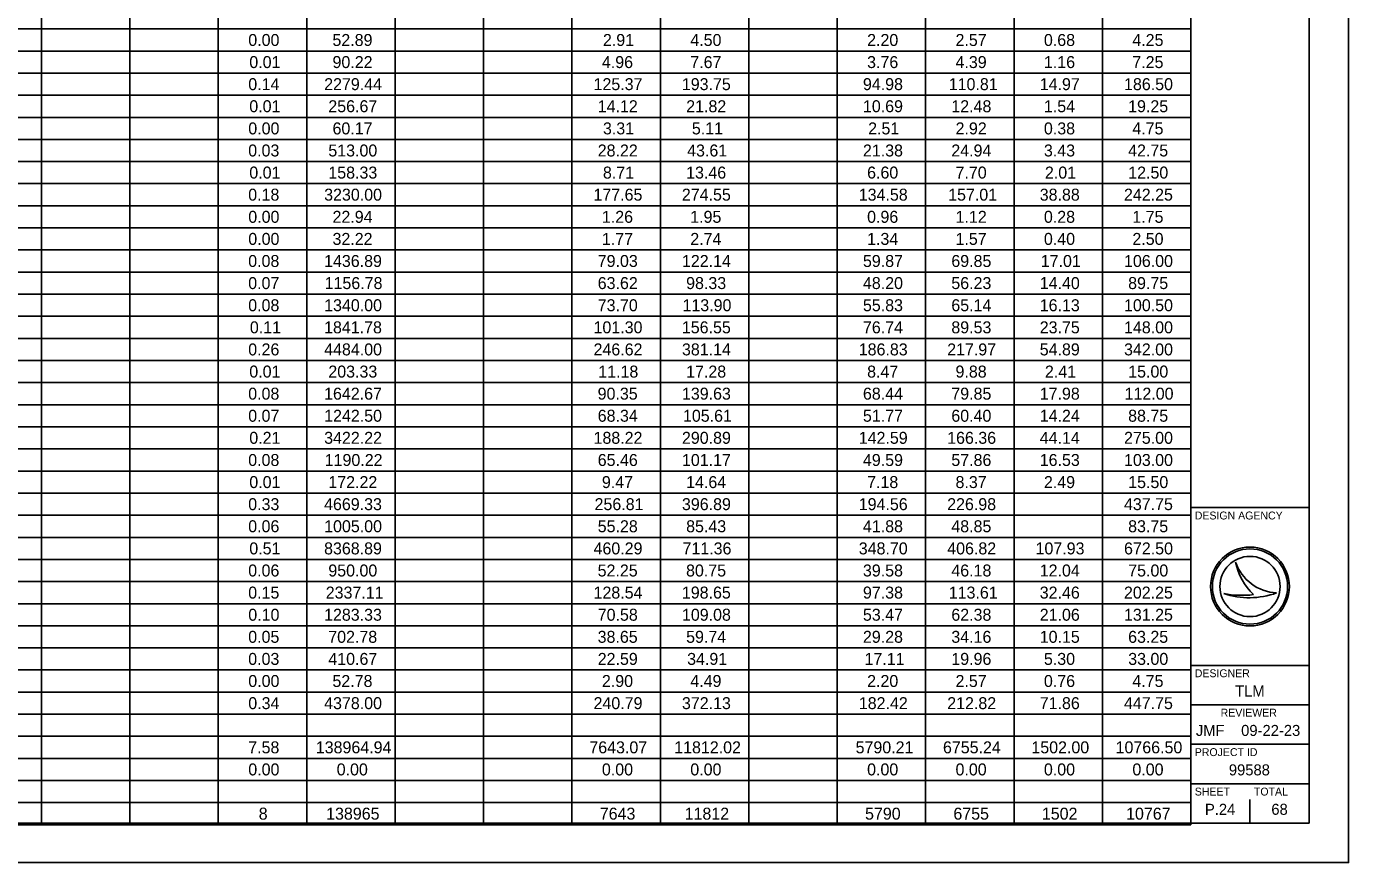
# Model space of a CAD drawing. Extents: x 0 to 34, y 0 to 22.
# Drawn here: x 17.23 to 34, y 0 to 10.6 of the extents above; entities that cross this region are included whole.
import ezdxf

# ---------------------------------------------------------------- set-up
doc = ezdxf.new("R2010")
doc.units = 0
for name, color, linetype in [('SH_Border', 7, 'Continuous'), ('SH_Cut_Line', 7, 'Continuous'), ('SH_Data', 7, 'Continuous'), ('SH_Text', 7, 'Continuous')]:
    doc.layers.add(name, color=color, linetype=linetype)

msp = doc.modelspace()

# ---------------------------------------------------------------- linework, layer by layer
at = {"layer": 'SH_Border'}
for p, q in [((32, 0.5), (32, 21.5)), ((32, 4.5), (33.5, 4.5)), ((32, 2.5), (33.5, 2.5)), ((32, 2), (33.5, 2)), ((32, 1.5), (33.5, 1.5)), ((32, 1), (33.5, 1))]:
    msp.add_line(p, q, dxfattribs=at)
msp.add_lwpolyline([(1.5, 21.5), (33.5, 21.5), (33.5, 0.5), (1.5, 0.5)], close=True, dxfattribs=at)
at = {"layer": 'SH_Cut_Line'}
msp.add_lwpolyline([(0, 0), (34, 0), (34, 22), (0, 22)], close=True, dxfattribs=at)
at = {"layer": 'SH_Data'}
for p, q in [((32.567, 3.81), (32.567, 3.81)), ((32.417, 3.41), (32.417, 3.41)), ((32.75, 3.5), (32.75, 3.5)), ((33.087, 3.419), (33.087, 3.419)), ((32.375, 0.675), (32.375, 0.675)), ((32.75, 0.5), (32.75, 0.8))]:
    msp.add_line(p, q, dxfattribs=at)
for radius in [0.5, 0.477, 0.477, 0.382]:
    msp.add_circle((32.75, 3.5), radius, dxfattribs=at)
for centre, radius, start, end in [((33.116, 3.998), 0.58, 198.9257, 198.9319), ((33.347, 3.97), 0.796, 191.6379, 191.6421), ((33.116, 3.998), 0.58, 198.9319, 267.1657), ((33.347, 3.97), 0.796, 191.6421, 226.0947), ((32.739, 4.37), 1.013, 251.4576, 290.0832), ((32.648, 4.654), 1.266, 259.4964, 259.4995), ((32.739, 4.37), 1.013, 251.4527, 251.4576), ((32.648, 4.654), 1.266, 259.4995, 276.6672)]:
    msp.add_arc(centre, radius, start, end, dxfattribs=at)
at = {"layer": 'SH_Text'}
for p, q in [((17.426, 21.5), (17.426, 0.48)), ((18.547, 21.5), (18.547, 0.48)), ((19.668, 21.5), (19.668, 0.48)), ((20.789, 21.5), (20.789, 0.48)), ((21.91, 21.5), (21.91, 0.48)), ((23.031, 21.5), (23.031, 0.48)), ((24.152, 21.5), (24.152, 0.48)), ((25.274, 21.5), (25.274, 0.48)), ((26.395, 21.5), (26.395, 0.48)), ((27.516, 21.5), (27.516, 0.48)), ((28.637, 21.5), (28.637, 0.48)), ((29.758, 21.5), (29.758, 0.48)), ((30.879, 21.5), (30.879, 0.48)), ((32, 21.5), (32, 0.48)), ((1.5, 10.569), (32, 10.569)), ((1.5, 10.289), (32, 10.289)), ((1.5, 10.009), (32, 10.009)), ((1.5, 9.729), (32, 9.729)), ((1.5, 9.448), (32, 9.448)), ((1.5, 9.168), (32, 9.168)), ((1.5, 8.888), (32, 8.888)), ((1.5, 8.608), (32, 8.608)), ((1.5, 8.327), (32, 8.327)), ((1.5, 8.047), (32, 8.047)), ((1.5, 7.767), (32, 7.767)), ((1.5, 7.486), (32, 7.486)), ((1.5, 7.206), (32, 7.206)), ((1.5, 6.926), (32, 6.926)), ((1.5, 6.646), (32, 6.646)), ((1.5, 6.365), (32, 6.365)), ((1.5, 6.085), (32, 6.085)), ((1.5, 5.805), (32, 5.805)), ((1.5, 5.525), (32, 5.525)), ((1.5, 5.244), (32, 5.244)), ((1.5, 4.964), (32, 4.964)), ((1.5, 4.684), (32, 4.684)), ((1.5, 4.404), (32, 4.404)), ((1.5, 4.123), (32, 4.123)), ((1.5, 3.843), (32, 3.843)), ((1.5, 3.563), (32, 3.563)), ((1.5, 3.282), (32, 3.282)), ((1.5, 3.002), (32, 3.002)), ((1.5, 2.722), (32, 2.722)), ((1.5, 2.442), (32, 2.442)), ((1.5, 2.161), (32, 2.161)), ((1.5, 1.881), (32, 1.881)), ((1.5, 1.601), (32, 1.601)), ((1.5, 1.321), (32, 1.321)), ((1.5, 1.04), (32, 1.04)), ((1.5, 0.76), (32, 0.76)), ((1.5, 0.48), (32, 0.48))]:
    msp.add_line(p, q, dxfattribs=at)

# ---------------------------------------------------------------- texts
at = {"layer": 'SH_Data'}
for s, height, p in [('DESIGN AGENCY', 0.1, (32.05, 4.35)), ('DESIGNER', 0.1, (32.05, 2.35)), ('TLM', 0.14, (32.562, 2.105)), ('REVIEWER', 0.1, (32.378, 1.85)), ('JMF', 0.14, (32.064, 1.605)), ('09-22-23', 0.14, (32.638, 1.605)), ('PROJECT ID', 0.1, (32.05, 1.35)), ('99588', 0.14, (32.482, 1.105)), ('SHEET', 0.1, (32.05, 0.85)), ('TOTAL', 0.1, (32.8, 0.85)), ('P.24', 0.14, (32.179, 0.605)), ('68', 0.14, (33.021, 0.605))]:
    msp.add_text(s, height=height, dxfattribs=at).set_placement(p)
at = {"layer": 'SH_Text'}
for s, height, p in [('0.00', 0.1517, (20.048, 10.353)), ('52.89', 0.1517, (21.115, 10.353)), ('2.91', 0.1517, (24.545, 10.353)), ('4.50', 0.1517, (25.653, 10.353)), ('2.20', 0.1517, (27.895, 10.353)), ('2.57', 0.1517, (29.016, 10.353)), ('0.68', 0.1517, (30.137, 10.353)), ('4.25', 0.1517, (31.258, 10.353)), ('0.01', 0.1517, (20.061, 10.073)), ('90.22', 0.1517, (21.116, 10.073)), ('4.96', 0.1517, (24.532, 10.073)), ('7.67', 0.1517, (25.653, 10.073)), ('3.76', 0.1517, (27.895, 10.073)), ('4.39', 0.1517, (29.016, 10.073)), ('1.16', 0.1517, (30.137, 10.073)), ('7.25', 0.1517, (31.258, 10.073)), ('0.14', 0.1517, (20.048, 9.793)), ('2279.44', 0.1517, (21.01, 9.793)), ('125.37', 0.1517, (24.426, 9.793)), ('193.75', 0.1517, (25.546, 9.793)), ('94.98', 0.1517, (27.842, 9.793)), ('110.81', 0.1517, (28.93, 9.793)), ('14.97', 0.1517, (30.084, 9.793)), ('186.50', 0.1517, (31.153, 9.793)), ('0.01', 0.1517, (20.061, 9.513)), ('256.67', 0.1517, (21.063, 9.513)), ('14.12', 0.1517, (24.479, 9.513)), ('21.82', 0.1517, (25.601, 9.513)), ('10.69', 0.1517, (27.842, 9.513)), ('12.48', 0.1517, (28.963, 9.513)), ('1.54', 0.1517, (30.137, 9.513)), ('19.25', 0.1517, (31.205, 9.513)), ('0.00', 0.1517, (20.048, 9.232)), ('60.17', 0.1517, (21.116, 9.232)), ('3.31', 0.1517, (24.545, 9.232)), ('5.11', 0.1517, (25.673, 9.232)), ('2.51', 0.1517, (27.908, 9.232)), ('2.92', 0.1517, (29.017, 9.232)), ('0.38', 0.1517, (30.137, 9.232)), ('4.75', 0.1517, (31.258, 9.232)), ('0.03', 0.1517, (20.047, 8.952)), ('513.00', 0.1517, (21.063, 8.952)), ('28.22', 0.1517, (24.479, 8.952)), ('43.61', 0.1517, (25.613, 8.952)), ('21.38', 0.1517, (27.842, 8.952)), ('24.94', 0.1517, (28.963, 8.952)), ('3.43', 0.1517, (30.137, 8.952)), ('42.75', 0.1517, (31.205, 8.952)), ('0.01', 0.1517, (20.061, 8.672)), ('158.33', 0.1517, (21.063, 8.672)), ('8.71', 0.1517, (24.545, 8.672)), ('13.46', 0.1517, (25.6, 8.672)), ('6.60', 0.1517, (27.895, 8.672)), ('7.70', 0.1517, (29.016, 8.672)), ('2.01', 0.1517, (30.15, 8.672)), ('12.50', 0.1517, (31.206, 8.672)), ('0.18', 0.1517, (20.047, 8.392)), ('3230.00', 0.1517, (21.01, 8.392)), ('177.65', 0.1517, (24.425, 8.392)), ('274.55', 0.1517, (25.546, 8.392)), ('134.58', 0.1517, (27.789, 8.392)), ('157.01', 0.1517, (28.923, 8.392)), ('38.88', 0.1517, (30.084, 8.392)), ('242.25', 0.1517, (31.152, 8.392)), ('0.00', 0.1517, (20.048, 8.111)), ('22.94', 0.1517, (21.116, 8.111)), ('1.26', 0.1517, (24.532, 8.111)), ('1.95', 0.1517, (25.652, 8.111)), ('0.96', 0.1517, (27.895, 8.111)), ('1.12', 0.1517, (29.017, 8.111)), ('0.28', 0.1517, (30.137, 8.111)), ('1.75', 0.1517, (31.258, 8.111)), ('0.00', 0.1517, (20.048, 7.831)), ('32.22', 0.1517, (21.116, 7.831)), ('1.77', 0.1517, (24.532, 7.831)), ('2.74', 0.1517, (25.653, 7.831)), ('1.34', 0.1517, (27.895, 7.831)), ('1.57', 0.1517, (29.016, 7.831)), ('0.40', 0.1517, (30.137, 7.831)), ('2.50', 0.1517, (31.259, 7.831)), ('0.08', 0.1517, (20.047, 7.551)), ('1436.89', 0.1517, (21.009, 7.551)), ('79.03', 0.1517, (24.479, 7.551)), ('122.14', 0.1517, (25.547, 7.551)), ('59.87', 0.1517, (27.842, 7.551)), ('69.85', 0.1517, (28.963, 7.551)), ('17.01', 0.1517, (30.097, 7.551)), ('106.00', 0.1517, (31.153, 7.551)), ('0.07', 0.1517, (20.047, 7.271)), ('1156.78', 0.1517, (21.016, 7.271)), ('63.62', 0.1517, (24.479, 7.271)), ('98.33', 0.1517, (25.6, 7.271)), ('48.20', 0.1517, (27.842, 7.271)), ('56.23', 0.1517, (28.963, 7.271)), ('14.40', 0.1517, (30.084, 7.271)), ('89.75', 0.1517, (31.205, 7.271)), ('0.08', 0.1517, (20.047, 6.99)), ('1340.00', 0.1517, (21.01, 6.99)), ('73.70', 0.1517, (24.479, 6.99)), ('113.90', 0.1517, (25.554, 6.99)), ('55.83', 0.1517, (27.842, 6.99)), ('65.14', 0.1517, (28.963, 6.99)), ('16.13', 0.1517, (30.084, 6.99)), ('100.50', 0.1517, (31.153, 6.99)), ('0.11', 0.1517, (20.068, 6.71)), ('1841.78', 0.1517, (21.009, 6.71)), ('101.30', 0.1517, (24.426, 6.71)), ('156.55', 0.1517, (25.546, 6.71)), ('76.74', 0.1517, (27.842, 6.71)), ('89.53', 0.1517, (28.963, 6.71)), ('23.75', 0.1517, (30.084, 6.71)), ('148.00', 0.1517, (31.153, 6.71)), ('0.26', 0.1517, (20.047, 6.43)), ('4484.00', 0.1517, (21.01, 6.43)), ('246.62', 0.1517, (24.426, 6.43)), ('381.14', 0.1517, (25.547, 6.43)), ('186.83', 0.1517, (27.789, 6.43)), ('217.97', 0.1517, (28.91, 6.43)), ('54.89', 0.1517, (30.084, 6.43)), ('342.00', 0.1517, (31.153, 6.43)), ('0.01', 0.1517, (20.061, 6.149)), ('203.33', 0.1517, (21.063, 6.149)), ('11.18', 0.1517, (24.486, 6.149)), ('17.28', 0.1517, (25.6, 6.149)), ('8.47', 0.1517, (27.895, 6.149)), ('9.88', 0.1517, (29.016, 6.149)), ('2.41', 0.1517, (30.15, 6.149)), ('15.00', 0.1517, (31.206, 6.149)), ('0.08', 0.1517, (20.047, 5.869)), ('1642.67', 0.1517, (21.009, 5.869)), ('90.35', 0.1517, (24.478, 5.869)), ('139.63', 0.1517, (25.547, 5.869)), ('68.44', 0.1517, (27.842, 5.869)), ('79.85', 0.1517, (28.963, 5.869)), ('17.98', 0.1517, (30.084, 5.869)), ('112.00', 0.1517, (31.16, 5.869)), ('0.07', 0.1517, (20.047, 5.589)), ('1242.50', 0.1517, (21.01, 5.589)), ('68.34', 0.1517, (24.479, 5.589)), ('105.61', 0.1517, (25.56, 5.589)), ('51.77', 0.1517, (27.842, 5.589)), ('60.40', 0.1517, (28.963, 5.589)), ('14.24', 0.1517, (30.084, 5.589)), ('88.75', 0.1517, (31.205, 5.589)), ('0.21', 0.1517, (20.061, 5.309)), ('3422.22', 0.1517, (21.01, 5.309)), ('188.22', 0.1517, (24.426, 5.309)), ('290.89', 0.1517, (25.547, 5.309)), ('142.59', 0.1517, (27.789, 5.309)), ('166.36', 0.1517, (28.91, 5.309)), ('44.14', 0.1517, (30.084, 5.309)), ('275.00', 0.1517, (31.153, 5.309)), ('0.08', 0.1517, (20.047, 5.028)), ('1190.22', 0.1517, (21.017, 5.028)), ('65.46', 0.1517, (24.479, 5.028)), ('101.17', 0.1517, (25.547, 5.028)), ('49.59', 0.1517, (27.842, 5.028)), ('57.86', 0.1517, (28.963, 5.028)), ('16.53', 0.1517, (30.084, 5.028)), ('103.00', 0.1517, (31.153, 5.028)), ('0.01', 0.1517, (20.061, 4.748)), ('172.22', 0.1517, (21.063, 4.748)), ('9.47', 0.1517, (24.532, 4.748)), ('14.64', 0.1517, (25.6, 4.748)), ('7.18', 0.1517, (27.895, 4.748)), ('8.37', 0.1517, (29.016, 4.748)), ('2.49', 0.1517, (30.137, 4.748)), ('15.50', 0.1517, (31.206, 4.748)), ('0.33', 0.1517, (20.047, 4.468)), ('4669.33', 0.1517, (21.009, 4.468)), ('256.81', 0.1517, (24.439, 4.468)), ('396.89', 0.1517, (25.547, 4.468)), ('194.56', 0.1517, (27.789, 4.468)), ('226.98', 0.1517, (28.91, 4.468)), ('437.75', 0.1517, (31.152, 4.468)), ('0.06', 0.1517, (20.047, 4.188)), ('1005.00', 0.1517, (21.01, 4.188)), ('55.28', 0.1517, (24.479, 4.188)), ('85.43', 0.1517, (25.6, 4.188)), ('41.88', 0.1517, (27.842, 4.188)), ('48.85', 0.1517, (28.963, 4.188)), ('83.75', 0.1517, (31.205, 4.188)), ('0.51', 0.1517, (20.061, 3.907)), ('8368.89', 0.1517, (21.009, 3.907)), ('460.29', 0.1517, (24.426, 3.907)), ('711.36', 0.1517, (25.554, 3.907)), ('348.70', 0.1517, (27.789, 3.907)), ('406.82', 0.1517, (28.911, 3.907)), ('107.93', 0.1517, (30.031, 3.907)), ('672.50', 0.1517, (31.153, 3.907)), ('0.06', 0.1517, (20.047, 3.627)), ('950.00', 0.1517, (21.063, 3.627)), ('52.25', 0.1517, (24.478, 3.627)), ('80.75', 0.1517, (25.599, 3.627)), ('39.58', 0.1517, (27.842, 3.627)), ('46.18', 0.1517, (28.963, 3.627)), ('12.04', 0.1517, (30.084, 3.627)), ('75.00', 0.1517, (31.206, 3.627)), ('0.15', 0.1517, (20.047, 3.347)), ('2337.11', 0.1517, (21.03, 3.347)), ('128.54', 0.1517, (24.426, 3.347)), ('198.65', 0.1517, (25.546, 3.347)), ('97.38', 0.1517, (27.842, 3.347)), ('113.61', 0.1517, (28.93, 3.347)), ('32.46', 0.1517, (30.084, 3.347)), ('202.25', 0.1517, (31.152, 3.347)), ('0.10', 0.1517, (20.048, 3.066)), ('1283.33', 0.1517, (21.009, 3.066)), ('70.58', 0.1517, (24.479, 3.066)), ('109.08', 0.1517, (25.547, 3.066)), ('53.47', 0.1517, (27.842, 3.066)), ('62.38', 0.1517, (28.963, 3.066)), ('21.06', 0.1517, (30.084, 3.066)), ('131.25', 0.1517, (31.152, 3.066)), ('0.05', 0.1517, (20.047, 2.786)), ('702.78', 0.1517, (21.062, 2.786)), ('38.65', 0.1517, (24.478, 2.786)), ('59.74', 0.1517, (25.6, 2.786)), ('29.28', 0.1517, (27.842, 2.786)), ('34.16', 0.1517, (28.963, 2.786)), ('10.15', 0.1517, (30.084, 2.786)), ('63.25', 0.1517, (31.205, 2.786)), ('0.03', 0.1517, (20.047, 2.506)), ('410.67', 0.1517, (21.063, 2.506)), ('22.59', 0.1517, (24.479, 2.506)), ('34.91', 0.1517, (25.613, 2.506)), ('17.11', 0.1517, (27.862, 2.506)), ('19.96', 0.1517, (28.963, 2.506)), ('5.30', 0.1517, (30.137, 2.506)), ('33.00', 0.1517, (31.206, 2.506)), ('0.00', 0.1517, (20.048, 2.226)), ('52.78', 0.1517, (21.115, 2.226)), ('2.90', 0.1517, (24.532, 2.226)), ('4.49', 0.1517, (25.653, 2.226)), ('2.20', 0.1517, (27.895, 2.226)), ('2.57', 0.1517, (29.016, 2.226)), ('0.76', 0.1517, (30.137, 2.226)), ('4.75', 0.1517, (31.258, 2.226)), ('0.34', 0.1517, (20.048, 1.945)), ('4378.00', 0.1517, (21.01, 1.945)), ('240.79', 0.1517, (24.426, 1.945)), ('372.13', 0.1517, (25.547, 1.945)), ('182.42', 0.1517, (27.79, 1.945)), ('212.82', 0.1517, (28.911, 1.945)), ('71.86', 0.1517, (30.084, 1.945)), ('447.75', 0.1517, (31.152, 1.945)), ('7.58', 0.1517, (20.047, 1.385)), ('138964.94', 0.1517, (20.904, 1.385)), ('7643.07', 0.1517, (24.373, 1.385)), ('11812.02', 0.1517, (25.449, 1.385)), ('5790.21', 0.1517, (27.749, 1.385)), ('6755.24', 0.1517, (28.857, 1.385)), ('1502.00', 0.1517, (29.978, 1.385)), ('10766.50', 0.1517, (31.046, 1.385)), ('0.00', 0.1517, (20.048, 1.105)), ('0.00', 0.1517, (21.169, 1.105)), ('0.00', 0.1517, (24.532, 1.105)), ('0.00', 0.1517, (25.653, 1.105)), ('0.00', 0.1517, (27.895, 1.105)), ('0.00', 0.1517, (29.016, 1.105)), ('0.00', 0.1517, (30.137, 1.105)), ('0.00', 0.1517, (31.259, 1.105)), ('8', 0.152, (20.18, 0.544)), ('138965', 0.1517, (21.035, 0.544)), ('7643', 0.1517, (24.505, 0.544)), ('11812', 0.1517, (25.581, 0.544)), ('5790', 0.1517, (27.869, 0.544)), ('6755', 0.1517, (28.989, 0.544)), ('1502', 0.1517, (30.111, 0.544)), ('10767', 0.1517, (31.179, 0.544))]:
    msp.add_text(s, height=height, dxfattribs=at).set_placement(p)

doc.saveas('drawing.dxf')
